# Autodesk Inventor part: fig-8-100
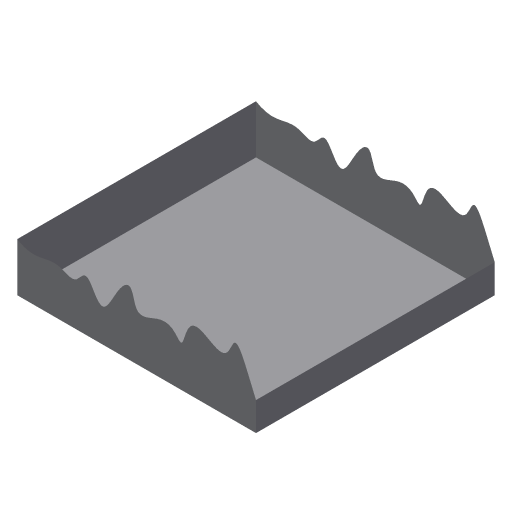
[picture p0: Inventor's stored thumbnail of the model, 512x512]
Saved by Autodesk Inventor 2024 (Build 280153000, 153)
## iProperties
Shininess: 64.0
Length Units: 11269
Angle Units: 11279
Time Units: 11290
Mass Units: 11283
Length Display Precision: 3
Angle Display Precision: 2
Compacted: True
Part Number: fig-8-100
Document SubType Name: Modeling
Created: 2002-12
Designer: deepak
Density: 1 g/cm^3
Material: Generic
Surface Area: 62.5725 cm^2
Appearance: Default
Density: 0.0
Volumn: 0.0
Area: 0.0
PropertySet Name: Model Information
Control State: 0
Master: False
Checked Out: False
Author: deepak
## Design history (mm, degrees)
sketch "Sketch1"
  geometry: L1 (-32.188, 30.089)-(27.812, 30.089); L2 (27.812, 30.089)-(27.812, -29.911); L3 (27.812, -29.911)-(-32.188, -29.911); L4 (-32.188, -29.911)-(-32.188, 30.089)
  constraints: 8 end point, 2 parallel, 1 horizontal, 1 perpendicular
  dimensions: "d0" = 60 distance of L1.start L1.end; "d1" = 60 distance of L3.end L1.start
extrude "Extrusion1" new body sketch "Sketch1" stored distance "d2" = 20; taper "d3" = 0 deg
sketch "Sketch2"
  geometry: 17 further points
  constraints: 17 other
extrude_surface "ExtrusionSrf1" sketch "Sketch2" dims "d4" = 70, "d5" = 0
split "Split1"
delete_face "Delete Face2"
body "Solid1"
body "Srf1"
